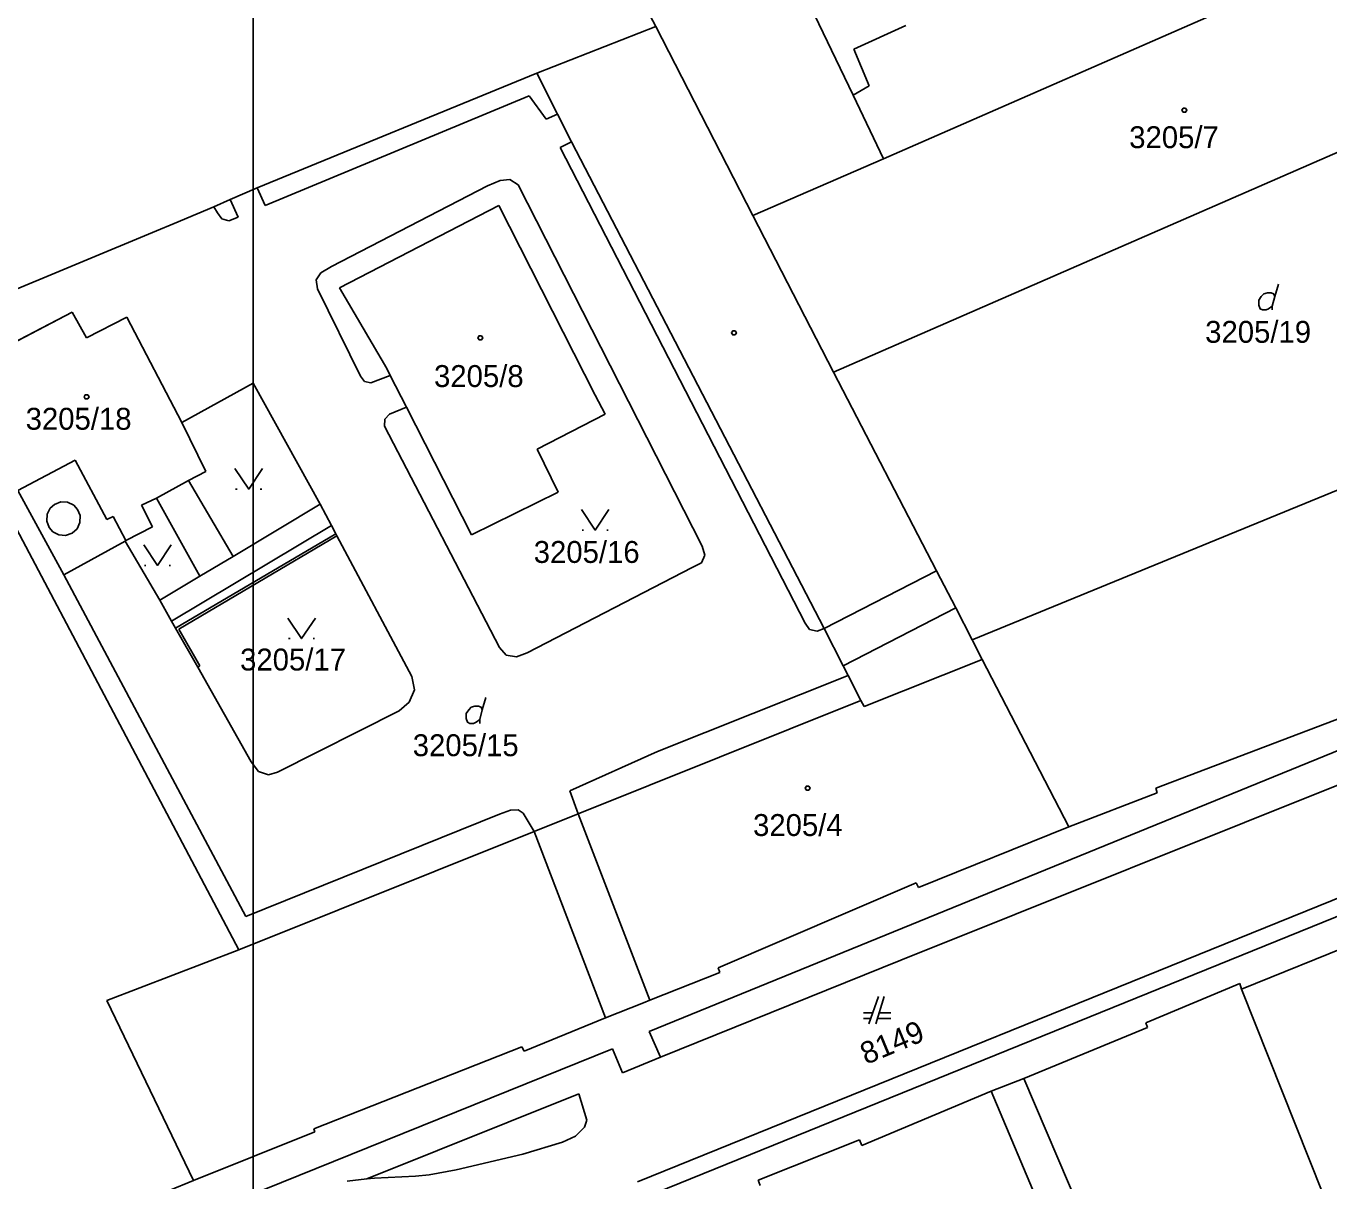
# Model space of a CAD drawing. Extents: x -263587 to -261993, y -1238795 to -1236748.
# Drawn here: x -263008.6 to -262913.5, y -1238717.7 to -1238633.3 of the extents above; entities that cross this region are included whole.
import ezdxf

# ---------------------------------------------------------------- set-up
doc = ezdxf.new("R2010")
doc.units = 0
doc.layers.add('Vrstva 1', color=7, linetype='Continuous')
doc.layers.add('Vrstva 51', color=7, linetype='Continuous')

msp = doc.modelspace()

# ---------------------------------------------------------------- linework, layer by layer
at = {"layer": 'Vrstva 1'}
for p, q in [((-262962.63, -1238633.33), (-262969.23, -1238620.88)), ((-262948.23, -1238638.35), (-262953.71, -1238626.95)), ((-262953.71, -1238626.95), (-262948.23, -1238638.35)), ((-262914.9, -1238629.37), (-262946.01, -1238643)), ((-262971.32, -1238636.73), (-262962.63, -1238633.33)), ((-262962.63, -1238633.33), (-262955.55, -1238647.13)), ((-262944.37, -1238633.27), (-262948.18, -1238634.99)), ((-262948.18, -1238634.99), (-262944.37, -1238633.27)), ((-262949.65, -1238658.59), (-262896.4, -1238635.32)), ((-262896.4, -1238635.32), (-262949.65, -1238658.59)), ((-262948.18, -1238634.99), (-262947.06, -1238637.67)), ((-262947.06, -1238637.67), (-262948.18, -1238634.99)), ((-262991.75, -1238645.12), (-262971.32, -1238636.73)), ((-262971.32, -1238636.73), (-262969.81, -1238639.74)), ((-262969.81, -1238639.74), (-262971.32, -1238636.73)), ((-262947.06, -1238637.67), (-262948.23, -1238638.35)), ((-262948.23, -1238638.35), (-262947.06, -1238637.67)), ((-262971.88, -1238638.4), (-262991.16, -1238646.41)), ((-262970.64, -1238640.1), (-262971.88, -1238638.4)), ((-262946.01, -1238643), (-262948.23, -1238638.35)), ((-262969.81, -1238639.74), (-262970.64, -1238640.1)), ((-262969.81, -1238639.74), (-262968.79, -1238641.75)), ((-262968.79, -1238641.75), (-262969.81, -1238639.74)), ((-262968.79, -1238641.75), (-262969.61, -1238642.18)), ((-262969.61, -1238642.18), (-262951.72, -1238676.93)), ((-262968.79, -1238641.75), (-262950.35, -1238677.31)), ((-262950.35, -1238677.31), (-262968.79, -1238641.75)), ((-262955.55, -1238647.13), (-262946.01, -1238643)), ((-262993.71, -1238645.98), (-262991.75, -1238645.12)), ((-262991.16, -1238646.41), (-262991.75, -1238645.12)), ((-262986.33, -1238650.86), (-262974.93, -1238644.97)), ((-262974.93, -1238644.97), (-262986.33, -1238650.86)), ((-262974.93, -1238644.97), (-262974, -1238644.58)), ((-262974, -1238644.58), (-262974.93, -1238644.97)), ((-262974, -1238644.58), (-262973.29, -1238644.52)), ((-262973.29, -1238644.52), (-262974, -1238644.58)), ((-262973.29, -1238644.52), (-262972.69, -1238644.91)), ((-262972.69, -1238644.91), (-262973.29, -1238644.52)), ((-262972.69, -1238644.91), (-262959.24, -1238671.29)), ((-262959.24, -1238671.29), (-262972.69, -1238644.91)), ((-262994.92, -1238646.51), (-262993.71, -1238645.98)), ((-262993.13, -1238647.27), (-262993.71, -1238645.98)), ((-262997.81, -1238647.72), (-262996.13, -1238647.01)), ((-262996.13, -1238647.01), (-262994.92, -1238646.51)), ((-262994.92, -1238646.51), (-262994.65, -1238646.94)), ((-262994.65, -1238646.94), (-262994.33, -1238647.39)), ((-262974.09, -1238646.42), (-262985.73, -1238652.42)), ((-262985.73, -1238652.42), (-262974.09, -1238646.42)), ((-262967.06, -1238660.26), (-262974.09, -1238646.42)), ((-262974.09, -1238646.42), (-262967.06, -1238660.26)), ((-262949.65, -1238658.59), (-262955.55, -1238647.13)), ((-262999.1, -1238648.26), (-262997.81, -1238647.72)), ((-262994.33, -1238647.39), (-262993.83, -1238647.54)), ((-262993.83, -1238647.54), (-262993.13, -1238647.27)), ((-263016.81, -1238655.62), (-262999.1, -1238648.26)), ((-262987.11, -1238651.34), (-262986.33, -1238650.86)), ((-262986.33, -1238650.86), (-262987.11, -1238651.34)), ((-262987.44, -1238651.83), (-262987.11, -1238651.34)), ((-262987.11, -1238651.34), (-262987.44, -1238651.83)), ((-262987.35, -1238652.5), (-262987.44, -1238651.83)), ((-262987.44, -1238651.83), (-262987.35, -1238652.5)), ((-262984.21, -1238658.88), (-262987.35, -1238652.5)), ((-262987.35, -1238652.5), (-262984.21, -1238658.88)), ((-262985.73, -1238652.42), (-262982.29, -1238658.32)), ((-262982.29, -1238658.32), (-262985.73, -1238652.42)), ((-262917.43, -1238653.05), (-262917.16, -1238652.15)), ((-263013.53, -1238658.53), (-263005.27, -1238654.19)), ((-263005.27, -1238654.19), (-263013.53, -1238658.53)), ((-263005.27, -1238654.19), (-263004.22, -1238656.07)), ((-263004.22, -1238656.07), (-263005.27, -1238654.19)), ((-263004.22, -1238656.07), (-263001.28, -1238654.57)), ((-263001.28, -1238654.57), (-263004.22, -1238656.07)), ((-263001.28, -1238654.57), (-262997.26, -1238662.26)), ((-262997.26, -1238662.26), (-263001.28, -1238654.57)), ((-262982.29, -1238658.32), (-262982.03, -1238658.83)), ((-262982.03, -1238658.83), (-262982.29, -1238658.32)), ((-262942.14, -1238673.1), (-262949.65, -1238658.59)), ((-262949.65, -1238658.59), (-262942.14, -1238673.1)), ((-262939.53, -1238678.14), (-262889.69, -1238657.71)), ((-262889.69, -1238657.71), (-262939.53, -1238678.14)), ((-262997.26, -1238662.26), (-262992.04, -1238659.39)), ((-262992.04, -1238659.39), (-262997.26, -1238662.26)), ((-262992.04, -1238659.39), (-262987.16, -1238668.24)), ((-262987.16, -1238668.24), (-262992.04, -1238659.39)), ((-262983.91, -1238659.27), (-262984.21, -1238658.88)), ((-262984.21, -1238658.88), (-262983.91, -1238659.27)), ((-262983.46, -1238659.37), (-262983.91, -1238659.27)), ((-262983.91, -1238659.27), (-262983.46, -1238659.37)), ((-262982.03, -1238658.83), (-262983.46, -1238659.37)), ((-262983.46, -1238659.37), (-262982.03, -1238658.83)), ((-262982.03, -1238658.83), (-262980.85, -1238661.13)), ((-262980.85, -1238661.13), (-262982.03, -1238658.83)), ((-262966.34, -1238661.65), (-262967.06, -1238660.26)), ((-262967.06, -1238660.26), (-262966.34, -1238661.65)), ((-262982.09, -1238661.66), (-262980.85, -1238661.13)), ((-262980.85, -1238661.13), (-262982.09, -1238661.66)), ((-262980.85, -1238661.13), (-262976.09, -1238670.46)), ((-262976.09, -1238670.46), (-262980.85, -1238661.13)), ((-262997.26, -1238662.26), (-262995.51, -1238665.84)), ((-262995.51, -1238665.84), (-262997.26, -1238662.26)), ((-262982.44, -1238662.52), (-262982.42, -1238662.03)), ((-262982.42, -1238662.03), (-262982.44, -1238662.52)), ((-262982.42, -1238662.03), (-262982.09, -1238661.66)), ((-262982.09, -1238661.66), (-262982.42, -1238662.03)), ((-262971.31, -1238664.21), (-262966.34, -1238661.65)), ((-262966.34, -1238661.65), (-262971.31, -1238664.21)), ((-262974.05, -1238678.69), (-262982.44, -1238662.52)), ((-262982.44, -1238662.52), (-262974.05, -1238678.69)), ((-262969.77, -1238667.36), (-262971.31, -1238664.21)), ((-262971.31, -1238664.21), (-262969.77, -1238667.36)), ((-263009.23, -1238667.22), (-263005.04, -1238665.02)), ((-263005.04, -1238665.02), (-263002.72, -1238669.36)), ((-262995.51, -1238665.84), (-262996.76, -1238666.51)), ((-262996.76, -1238666.51), (-262995.51, -1238665.84)), ((-262996.76, -1238666.51), (-262999.11, -1238667.78)), ((-262996.76, -1238666.51), (-262993.51, -1238672.05)), ((-262993.51, -1238672.05), (-262996.76, -1238666.51)), ((-262993.32, -1238667.13), (-262993.22, -1238667.13)), ((-262991.52, -1238667.13), (-262991.42, -1238667.13)), ((-262993.08, -1238700.78), (-263010.47, -1238667.87)), ((-263005.88, -1238673.39), (-263009.23, -1238667.22)), ((-263009.23, -1238667.22), (-263005.88, -1238673.39)), ((-263006.55, -1238668.25), (-263006.09, -1238668.06)), ((-263006.09, -1238668.06), (-263005.59, -1238668.08)), ((-263005.59, -1238668.08), (-263005.14, -1238668.3)), ((-262999.11, -1238667.78), (-263000.2, -1238668.31)), ((-263000.2, -1238668.31), (-262999.11, -1238667.78)), ((-262995.93, -1238673.5), (-262999.11, -1238667.78)), ((-262999.11, -1238667.78), (-262995.93, -1238673.5)), ((-262976.09, -1238670.46), (-262969.77, -1238667.36)), ((-262969.77, -1238667.36), (-262976.09, -1238670.46)), ((-263007.12, -1238669.47), (-263007.09, -1238668.97)), ((-263007.09, -1238668.97), (-263006.87, -1238668.52)), ((-263006.87, -1238668.52), (-263006.55, -1238668.25)), ((-263005.14, -1238668.3), (-263004.87, -1238668.61)), ((-263004.87, -1238668.61), (-263004.67, -1238669.06)), ((-263004.67, -1238669.06), (-263004.69, -1238669.56)), ((-263000.2, -1238668.31), (-262999.39, -1238669.88)), ((-262999.39, -1238669.88), (-263000.2, -1238668.31)), ((-262993.51, -1238672.05), (-262987.16, -1238668.24)), ((-262987.16, -1238668.24), (-262986.33, -1238669.78)), ((-262986.33, -1238669.78), (-262987.16, -1238668.24)), ((-263006.93, -1238669.93), (-263007.12, -1238669.47)), ((-263006.68, -1238670.24), (-263006.93, -1238669.93)), ((-263004.9, -1238670.02), (-263005.27, -1238670.35)), ((-263004.69, -1238669.56), (-263004.9, -1238670.02)), ((-263002.72, -1238669.36), (-263002.27, -1238669.13)), ((-263002.27, -1238669.13), (-263001.34, -1238670.88)), ((-262999.39, -1238669.88), (-263001.34, -1238670.88)), ((-263001.34, -1238670.88), (-262999.39, -1238669.88)), ((-262998, -1238676.77), (-262986.33, -1238669.78)), ((-262986.33, -1238669.78), (-262986, -1238670.39)), ((-262986, -1238670.39), (-262986.33, -1238669.78)), ((-263006.24, -1238670.47), (-263006.68, -1238670.24)), ((-263005.74, -1238670.51), (-263006.24, -1238670.47)), ((-263001.4, -1238670.92), (-263005.88, -1238673.39)), ((-263005.88, -1238673.39), (-263001.4, -1238670.92)), ((-263005.27, -1238670.35), (-263005.74, -1238670.51)), ((-263001.34, -1238670.88), (-263001.4, -1238670.92)), ((-263001.4, -1238670.92), (-263001.34, -1238670.88)), ((-262998.85, -1238675.25), (-263001.4, -1238670.92)), ((-263001.4, -1238670.92), (-262998.85, -1238675.25)), ((-262986, -1238670.39), (-262997.71, -1238677.29)), ((-262985.92, -1238670.53), (-262997.46, -1238677.36)), ((-262986, -1238670.39), (-262985.92, -1238670.53)), ((-262985.92, -1238670.53), (-262986, -1238670.39)), ((-262985.92, -1238670.53), (-262980.46, -1238680.82)), ((-262980.46, -1238680.82), (-262985.92, -1238670.53)), ((-262968.01, -1238670.12), (-262967.91, -1238670.12)), ((-262966.21, -1238670.12), (-262966.11, -1238670.12)), ((-262959.24, -1238671.29), (-262959.06, -1238671.96)), ((-262959.06, -1238671.96), (-262959.24, -1238671.29)), ((-262999.97, -1238672.7), (-262999.87, -1238672.7)), ((-262998.17, -1238672.7), (-262998.07, -1238672.7)), ((-262993.51, -1238672.05), (-262995.93, -1238673.5)), ((-262995.93, -1238673.5), (-262993.51, -1238672.05)), ((-262959.98, -1238672.86), (-262972.02, -1238679.08)), ((-262972.02, -1238679.08), (-262959.98, -1238672.86)), ((-262959.29, -1238672.51), (-262959.98, -1238672.86)), ((-262959.98, -1238672.86), (-262959.29, -1238672.51)), ((-262959.06, -1238671.96), (-262959.29, -1238672.51)), ((-262959.29, -1238672.51), (-262959.06, -1238671.96)), ((-262992.58, -1238698.36), (-263005.88, -1238673.39)), ((-262995.93, -1238673.5), (-262998.85, -1238675.25)), ((-262950.35, -1238677.31), (-262942.14, -1238673.1)), ((-262940.73, -1238675.81), (-262942.14, -1238673.1)), ((-262942.14, -1238673.1), (-262940.73, -1238675.81)), ((-262998, -1238676.77), (-262998.85, -1238675.25)), ((-262998.85, -1238675.25), (-262998, -1238676.77)), ((-262948.95, -1238680.03), (-262940.73, -1238675.81)), ((-262939.53, -1238678.14), (-262940.73, -1238675.81)), ((-262940.73, -1238675.81), (-262939.53, -1238678.14)), ((-262997.71, -1238677.29), (-262998, -1238676.77)), ((-262998, -1238676.77), (-262997.71, -1238677.29)), ((-262996.09, -1238680.14), (-262997.71, -1238677.29)), ((-262997.71, -1238677.29), (-262996.09, -1238680.14)), ((-262997.46, -1238677.36), (-262995.94, -1238680.05)), ((-262951.72, -1238676.93), (-262951.4, -1238677.39)), ((-262951.4, -1238677.39), (-262950.84, -1238677.51)), ((-262950.84, -1238677.51), (-262950.35, -1238677.31)), ((-262950.35, -1238677.31), (-262948.95, -1238680.03)), ((-262948.95, -1238680.03), (-262950.35, -1238677.31)), ((-262989.45, -1238678.05), (-262989.35, -1238678.05)), ((-262987.65, -1238678.05), (-262987.55, -1238678.05)), ((-262938.79, -1238679.58), (-262939.53, -1238678.14)), ((-262939.53, -1238678.14), (-262938.79, -1238679.58)), ((-262973.56, -1238679.27), (-262974.05, -1238678.69)), ((-262974.05, -1238678.69), (-262973.56, -1238679.27)), ((-262972.81, -1238679.37), (-262973.56, -1238679.27)), ((-262973.56, -1238679.27), (-262972.81, -1238679.37)), ((-262972.02, -1238679.08), (-262972.81, -1238679.37)), ((-262972.81, -1238679.37), (-262972.02, -1238679.08)), ((-262963.98, -1238717.73), (-262869.63, -1238679.5)), ((-262995.94, -1238680.05), (-262996.09, -1238680.14)), ((-262992.18, -1238687.04), (-262996.09, -1238680.14)), ((-262996.09, -1238680.14), (-262992.18, -1238687.04)), ((-262868.68, -1238680.43), (-262963.45, -1238718.87)), ((-262948.95, -1238680.03), (-262948.59, -1238680.74)), ((-262948.59, -1238680.74), (-262948.95, -1238680.03)), ((-262947.42, -1238683.01), (-262938.79, -1238679.58)), ((-262938.79, -1238679.58), (-262947.42, -1238683.01)), ((-262932.47, -1238691.8), (-262938.79, -1238679.58)), ((-262938.79, -1238679.58), (-262932.47, -1238691.8)), ((-262980.46, -1238680.82), (-262980.27, -1238681.79)), ((-262980.27, -1238681.79), (-262980.46, -1238680.82)), ((-262948.59, -1238680.74), (-262962.52, -1238686.3)), ((-262948.59, -1238680.74), (-262947.65, -1238682.57)), ((-262947.65, -1238682.57), (-262948.59, -1238680.74)), ((-262980.27, -1238681.79), (-262980.64, -1238682.7)), ((-262980.64, -1238682.7), (-262980.27, -1238681.79)), ((-262975.31, -1238683.25), (-262975.04, -1238682.35)), ((-262963.13, -1238706.75), (-262902.85, -1238682.16)), ((-262981.38, -1238683.33), (-262990.26, -1238687.81)), ((-262990.26, -1238687.81), (-262981.38, -1238683.33)), ((-262980.64, -1238682.7), (-262981.38, -1238683.33)), ((-262981.38, -1238683.33), (-262980.64, -1238682.7)), ((-262968.3, -1238690.84), (-262947.65, -1238682.57)), ((-262947.65, -1238682.57), (-262968.3, -1238690.84)), ((-262947.65, -1238682.57), (-262947.42, -1238683.01)), ((-262947.42, -1238683.01), (-262947.65, -1238682.57)), ((-262909.66, -1238682.73), (-262926.12, -1238688.97)), ((-262926.12, -1238688.97), (-262909.66, -1238682.73)), ((-262901.91, -1238684.38), (-262944.75, -1238701.53)), ((-262991.64, -1238687.76), (-262992.18, -1238687.04)), ((-262992.18, -1238687.04), (-262991.64, -1238687.76)), ((-262962.52, -1238686.3), (-262968.91, -1238689.18)), ((-262990.93, -1238688), (-262991.64, -1238687.76)), ((-262991.64, -1238687.76), (-262990.93, -1238688)), ((-262990.26, -1238687.81), (-262990.93, -1238688)), ((-262990.93, -1238688), (-262990.26, -1238687.81)), ((-262926.12, -1238688.97), (-262926.02, -1238689.32)), ((-262926.02, -1238689.32), (-262926.12, -1238688.97)), ((-262968.91, -1238689.18), (-262968.3, -1238690.84)), ((-262926.02, -1238689.32), (-262932.47, -1238691.8)), ((-262932.47, -1238691.8), (-262926.02, -1238689.32)), ((-262974.05, -1238690.87), (-262992.58, -1238698.36)), ((-262973.24, -1238690.59), (-262974.05, -1238690.87)), ((-262972.69, -1238690.56), (-262973.24, -1238690.59)), ((-262972.33, -1238690.81), (-262972.69, -1238690.56)), ((-262971.51, -1238692.13), (-262972.33, -1238690.81)), ((-262971.51, -1238692.13), (-262968.3, -1238690.84)), ((-262968.3, -1238690.84), (-262971.51, -1238692.13)), ((-262968.3, -1238690.84), (-262963.07, -1238704.47)), ((-262932.47, -1238691.8), (-262943.46, -1238696.23)), ((-262943.46, -1238696.23), (-262932.47, -1238691.8)), ((-262993.08, -1238700.78), (-262971.51, -1238692.13)), ((-262971.51, -1238692.13), (-262993.08, -1238700.78)), ((-262966.3, -1238705.75), (-262971.51, -1238692.13)), ((-262943.63, -1238695.89), (-262958.07, -1238702.1)), ((-262958.07, -1238702.1), (-262943.63, -1238695.89)), ((-262943.46, -1238696.23), (-262943.63, -1238695.89)), ((-262943.63, -1238695.89), (-262943.46, -1238696.23)), ((-262919.85, -1238703.65), (-262909.17, -1238699.33)), ((-262909.17, -1238699.33), (-262919.85, -1238703.65)), ((-263002.72, -1238704.48), (-262993.08, -1238700.78)), ((-262944.75, -1238701.53), (-262962.29, -1238708.63)), ((-262958.07, -1238702.1), (-262957.95, -1238702.43)), ((-262957.95, -1238702.43), (-262958.07, -1238702.1)), ((-262957.95, -1238702.43), (-262963.07, -1238704.47)), ((-262963.07, -1238704.47), (-262957.95, -1238702.43)), ((-262926.86, -1238706.12), (-262919.99, -1238703.25)), ((-262919.99, -1238703.25), (-262926.86, -1238706.12)), ((-262919.99, -1238703.25), (-262919.85, -1238703.65)), ((-262919.85, -1238703.65), (-262919.99, -1238703.25)), ((-262946.37, -1238704.2), (-262947.07, -1238706.2)), ((-262946.57, -1238706.2), (-262945.97, -1238704.2)), ((-262913.91, -1238718.59), (-262919.85, -1238703.65)), ((-262919.85, -1238703.65), (-262913.91, -1238718.59)), ((-262996.41, -1238717.63), (-263002.72, -1238704.48)), ((-262963.54, -1238704.66), (-262966.3, -1238705.75)), ((-262966.3, -1238705.75), (-262963.54, -1238704.66)), ((-262963.07, -1238704.47), (-262963.54, -1238704.66)), ((-262963.54, -1238704.66), (-262963.07, -1238704.47)), ((-262966.3, -1238705.75), (-262972.26, -1238708.2)), ((-262972.26, -1238708.2), (-262966.3, -1238705.75)), ((-262946.79, -1238705.4), (-262947.47, -1238705.4)), ((-262947.47, -1238705.8), (-262946.93, -1238705.8)), ((-262946.45, -1238705.8), (-262945.47, -1238705.8)), ((-262945.47, -1238705.4), (-262946.33, -1238705.4)), ((-262926.73, -1238706.46), (-262926.86, -1238706.12)), ((-262926.86, -1238706.12), (-262926.73, -1238706.46)), ((-262962.29, -1238708.63), (-262963.13, -1238706.75)), ((-262935.77, -1238710.19), (-262926.73, -1238706.46)), ((-262926.73, -1238706.46), (-262935.77, -1238710.19)), ((-263006.49, -1238724.44), (-262965.81, -1238708.03)), ((-262972.41, -1238707.87), (-262987.6, -1238713.86)), ((-262987.6, -1238713.86), (-262972.41, -1238707.87)), ((-262972.26, -1238708.2), (-262972.41, -1238707.87)), ((-262972.41, -1238707.87), (-262972.26, -1238708.2)), ((-262965.81, -1238708.03), (-262965.08, -1238709.78)), ((-262962.29, -1238708.63), (-262965.08, -1238709.78)), ((-262938.14, -1238711.12), (-262935.77, -1238710.19)), ((-262935.77, -1238710.19), (-262938.14, -1238711.12)), ((-262935.77, -1238710.19), (-262929.42, -1238725.02)), ((-262968.25, -1238711.3), (-262983.75, -1238717.52)), ((-262967.67, -1238713.22), (-262968.25, -1238711.3)), ((-262947.6, -1238715.07), (-262938.14, -1238711.12)), ((-262938.14, -1238711.12), (-262947.6, -1238715.07)), ((-262931.87, -1238726.01), (-262938.14, -1238711.12)), ((-262968.5, -1238714.39), (-262967.85, -1238713.73)), ((-262967.85, -1238713.73), (-262967.67, -1238713.22)), ((-262987.53, -1238714.09), (-262996.41, -1238717.63)), ((-262996.41, -1238717.63), (-262987.53, -1238714.09)), ((-262987.6, -1238713.86), (-262987.53, -1238714.09)), ((-262987.53, -1238714.09), (-262987.6, -1238713.86)), ((-262969.45, -1238714.84), (-262968.5, -1238714.39)), ((-262955.17, -1238717.62), (-262947.76, -1238714.66)), ((-262947.76, -1238714.66), (-262955.17, -1238717.62)), ((-262947.76, -1238714.66), (-262947.6, -1238715.07)), ((-262947.6, -1238715.07), (-262947.76, -1238714.66)), ((-262972.34, -1238715.71), (-262969.45, -1238714.84)), ((-262977.22, -1238716.86), (-262972.34, -1238715.71)), ((-262985.18, -1238717.69), (-262983.75, -1238717.52)), ((-262983.75, -1238717.52), (-262983.19, -1238717.46)), ((-262983.19, -1238717.46), (-262980.19, -1238717.31)), ((-262980.19, -1238717.31), (-262979.18, -1238717.23)), ((-262979.18, -1238717.23), (-262977.22, -1238716.86)), ((-263008.23, -1238722.48), (-262996.41, -1238717.63)), ((-262955.02, -1238718), (-262955.17, -1238717.62)), ((-262955.17, -1238717.62), (-262955.02, -1238718))]:
    msp.add_line(p, q, dxfattribs=at)
for points in [[(-262923.94, -1238639.3), (-262923.85, -1238639.45), (-262923.94, -1238639.6), (-262924.12, -1238639.6), (-262924.21, -1238639.45), (-262924.12, -1238639.3)], [(-262956.84, -1238655.57), (-262956.75, -1238655.72), (-262956.84, -1238655.87), (-262957.02, -1238655.87), (-262957.11, -1238655.72), (-262957.02, -1238655.57)], [(-262975.36, -1238655.92), (-262975.27, -1238656.07), (-262975.36, -1238656.22), (-262975.54, -1238656.22), (-262975.63, -1238656.07), (-262975.54, -1238655.92)], [(-263004.12, -1238660.24), (-263004.03, -1238660.39), (-263004.12, -1238660.54), (-263004.3, -1238660.54), (-263004.39, -1238660.39), (-263004.3, -1238660.24)], [(-262951.46, -1238688.82), (-262951.37, -1238688.97), (-262951.46, -1238689.12), (-262951.64, -1238689.12), (-262951.73, -1238688.97), (-262951.64, -1238688.82)]]:
    msp.add_lwpolyline(points, close=True, dxfattribs=at)
for points in [[(-262917.61, -1238654.04), (-262917.61, -1238653.77), (-262917.43, -1238653.05), (-262917.52, -1238652.87), (-262917.7, -1238652.78), (-262917.97, -1238652.78), (-262918.24, -1238652.87), (-262918.42, -1238653.05), (-262918.6, -1238653.32), (-262918.6, -1238653.68), (-262918.51, -1238653.95), (-262918.33, -1238654.04), (-262918.06, -1238654.04), (-262917.88, -1238653.95), (-262917.61, -1238653.77)], [(-262993.37, -1238665.63), (-262992.37, -1238667.13), (-262991.37, -1238665.63)], [(-262968.06, -1238668.62), (-262967.06, -1238670.12), (-262966.06, -1238668.62)], [(-263000.02, -1238671.2), (-262999.02, -1238672.7), (-262998.02, -1238671.2)], [(-262989.5, -1238676.55), (-262988.5, -1238678.05), (-262987.5, -1238676.55)], [(-262975.49, -1238684.24), (-262975.49, -1238683.97), (-262975.31, -1238683.25), (-262975.4, -1238683.07), (-262975.58, -1238682.98), (-262975.85, -1238682.98), (-262976.12, -1238683.07), (-262976.3, -1238683.25), (-262976.48, -1238683.52), (-262976.48, -1238683.88), (-262976.39, -1238684.15), (-262976.21, -1238684.24), (-262975.94, -1238684.24), (-262975.76, -1238684.15), (-262975.49, -1238683.97)]]:
    msp.add_lwpolyline(points, dxfattribs=at)
at = {"layer": 'Vrstva 51'}
msp.add_lwpolyline([(-262992.03, -1237088.09), (-262695.03, -1237088.09), (-262695.03, -1238768.09), (-262992.03, -1238768.09)], close=True, dxfattribs=at)

# ---------------------------------------------------------------- texts
at = {"layer": 'Vrstva 1'}
for s, p in [('3205/7', (-262928.062, -1238642.22)), ('3205/19', (-262922.513, -1238656.44)), ('3205/8', (-262978.832, -1238659.67)), ('3205/18', (-263008.657, -1238662.79)), ('3205/16', (-262971.551, -1238672.52)), ('3205/17', (-262992.997, -1238680.38)), ('3205/15', (-262980.387, -1238686.64)), ('3205/4', (-262955.532, -1238692.47))]:
    msp.add_text(s, height=1.6, dxfattribs=at).set_placement(p)
msp.add_text('8149', height=1.6, rotation=22.51724, dxfattribs=at).set_placement((-262947.283, -1238709.195))

doc.saveas('drawing.dxf')
